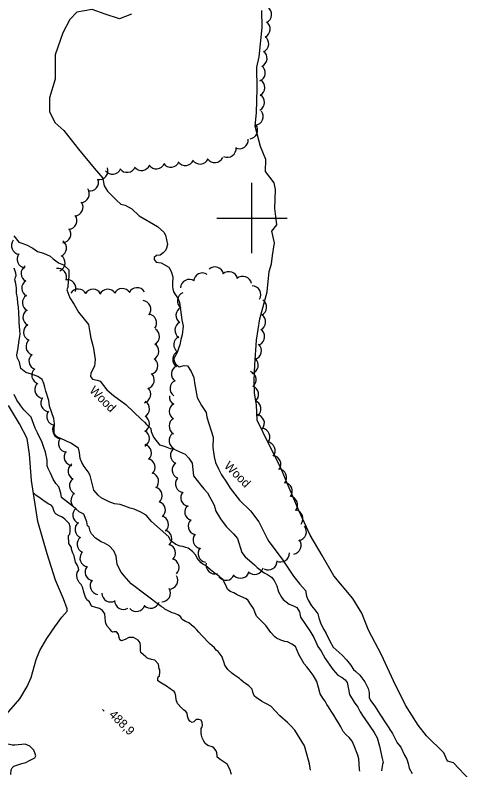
# Model space of a CAD drawing. Extents: x 642515 to 647219, y 6080136 to 6084356.
# Drawn here: x 643919.5 to 644074.3, y 6081612.4 to 6081869.2 of the extents above; entities that cross this region are included whole.
import ezdxf

# ---------------------------------------------------------------- set-up
doc = ezdxf.new("R2010")
doc.units = 0
for name, color, linetype in [('Level 1', 7, 'Continuous'), ('Level 19', 7, 'Continuous'), ('Level 2', 7, 'Continuous'), ('Level 3', 7, 'Continuous'), ('Level 4', 7, 'Continuous'), ('Level 44', 7, 'Continuous'), ('Level 61', 7, 'Continuous')]:
    doc.layers.add(name, color=color, linetype=linetype)

msp = doc.modelspace()

# ---------------------------------------------------------------- linework, layer by layer
at = {"layer": 'Level 1'}
for points in [[(643959.19, 6081869.49), (643955.1, 6081867.87), (643950.17, 6081869.49), (643945.82, 6081871.06), (643940.54, 6081870.21), (643938.14, 6081867.7), (643935.79, 6081863.14), (643933.19, 6081855.71), (643933.19, 6081847.35), (643931.26, 6081841.02), (643931.21, 6081836.42), (643933.07, 6081832.59), (643936.1, 6081829.89), (643941.14, 6081823.52), (643946.44, 6081817.09), (643949.41, 6081813.67)], [(643949.41, 6081813.67), (643949.41, 6081813.67), (643949.66, 6081812.23), (643949.88, 6081811.11), (643950.96, 6081809.23), (643954.05, 6081806.17), (643955.5, 6081804.88), (643956.98, 6081804.47), (643959.32, 6081803.31), (643961.8, 6081800.94), (643968, 6081797.24), (643970.13, 6081795.33), (643970.76, 6081794.32), (643971.42, 6081791.13), (643971.09, 6081789.9), (643970.72, 6081789.15), (643969.96, 6081788.3), (643968.95, 6081787.52), (643967.66, 6081787.45), (643966.81, 6081786.68), (643966.84, 6081786.03), (643967.54, 6081785.1), (643969.26, 6081784.95), (643971.85, 6081783.4), (643972.67, 6081781.91), (643973.25, 6081780.17), (643973.1, 6081777.78), (643973.12, 6081776.77), (643973.2, 6081776.01), (643973.46, 6081775.01), (643975.05, 6081772.6), (643975.52, 6081771.41), (643976.08, 6081767.25), (643976.25, 6081765.56), (643976.7, 6081763.33), (643976.38, 6081760.41), (643975.9, 6081758.85), (643975.6, 6081756.97), (643974.62, 6081754.18), (643973.59, 6081752.35), (643973.72, 6081751.47), (643974.18, 6081750.44), (643975.36, 6081749.54), (643977.04, 6081750.03), (643978.26, 6081749.86), (643979.42, 6081747.91), (643980.35, 6081745.86), (643980.61, 6081744.1), (643981.46, 6081739.06), (643982.99, 6081736.32)], [(643982.99, 6081736.32), (643984.57, 6081733.99), (643984.82, 6081732.39), (643986.9, 6081725.65), (643986.77, 6081722.1), (643987.28, 6081718.9), (643987.71, 6081716.99), (643988.8, 6081714.79), (643989.73, 6081712.74), (643991.48, 6081710.26), (643992.73, 6081708.23), (643995.87, 6081704.21), (643999.63, 6081700.55), (644002.43, 6081696.83), (644005.34, 6081691.18), (644005.88, 6081690.09), (644010.43, 6081684.05), (644014.22, 6081678.37), (644016.48, 6081675.6), (644017.35, 6081674.52), (644018.38, 6081673.44), (644018.65, 6081671.53), (644019.22, 6081670.11), (644020.45, 6081668.24), (644021.5, 6081666.85), (644022.55, 6081665.45), (644022.87, 6081664.1), (644023.54, 6081662.13), (644024.54, 6081660.17), (644025.43, 6081658.77), (644026.53, 6081656.41), (644027.78, 6081654.22), (644028.81, 6081653.31), (644030.85, 6081651.49), (644032.31, 6081649.88), (644033.7, 6081648.18), (644034.68, 6081646.55), (644035.45, 6081645.86), (644036.81, 6081644.65), (644038.56, 6081642.33), (644039.65, 6081640.13), (644039.97, 6081638.78), (644040.07, 6081637.02), (644040.53, 6081636), (644041.92, 6081634.14), (644043.7, 6081631.34), (644047.94, 6081624.81), (644048.57, 6081623.64), (644049.57, 6081621.68), (644050.79, 6081620.13), (644052.07, 6081617.47), (644052.79, 6081616.06)], [(643918.08, 6081610.83), (643918.15, 6081612.43), (643918.51, 6081613.17), (643919.12, 6081613.68), (643920.85, 6081614.26), (643921.88, 6081614.55), (643923.14, 6081614.94), (643924.47, 6081615.57), (643926.26, 6081616.55), (643926.55, 6081617.2), (643926.35, 6081617.83), (643925.96, 6081619.09), (643924.51, 6081620.52), (643922.95, 6081621.16), (643919.44, 6081620.81), (643918.56, 6081620.84), (643915.7, 6081621.56), (643915.14, 6081621.61), (643913.93, 6081621.79), (643911.5, 6081622.13), (643909.86, 6081622.68), (643909.14, 6081622.72), (643907.64, 6081623.6), (643905.57, 6081625.35)], [(644052.79, 6081616.06), (644053.28, 6081614.56), (644053.61, 6081613.05), (644054.68, 6081611.17)]]:
    msp.add_lwpolyline(points, dxfattribs=at)
at = {"layer": 'Level 19'}
msp.add_lwpolyline([(643915.97, 6081630.54), (643921.14, 6081636.58), (643923.62, 6081640.73), (643925.02, 6081643.85), (643926.73, 6081649.99), (643928.01, 6081653.06), (643930.29, 6081657.17), (643933.07, 6081661.13), (643935.48, 6081664.35), (643937.23, 6081666.39), (643937.3, 6081667.25), (643936, 6081670.63), (643933.27, 6081676.97), (643930.51, 6081685.96), (643927.31, 6081696.87), (643925.1, 6081710.9), (643924.49, 6081719.81), (643923.61, 6081725.13), (643921.08, 6081730.08), (643917.33, 6081736.42)], dxfattribs=at)
at = {"layer": 'Level 2'}
for points in [[(643919.07, 6081794.12), (643920.81, 6081791.96), (643921.47, 6081791.67), (643923.37, 6081791.05), (643925.54, 6081789.88), (643927.14, 6081788.76), (643929.19, 6081788.14), (643931.52, 6081787.14), (643932.54, 6081786.23), (643934.31, 6081784.95), (643935.97, 6081784.24), (643937.84, 6081782.57), (643937.81, 6081780.15), (643937.58, 6081778.52), (643937.44, 6081776.66), (643937.17, 6081775.68), (643938.13, 6081772.99), (643939.64, 6081770.74), (643941.16, 6081768.16), (643944.55, 6081763.92), (643944.83, 6081761.84), (643945.29, 6081759.28), (643946, 6081756.83), (643946.22, 6081755.71), (643946.75, 6081752.03), (643946.56, 6081749.77), (643945.32, 6081747.37), (643945.22, 6081746.23), (643945.83, 6081745.38), (643947.47, 6081744.99), (643948.54, 6081744.64), (643950.81, 6081741.7), (643953.02, 6081739.73), (643957.23, 6081736.74), (643962.61, 6081731.64), (643963.63, 6081730.73), (643964.25, 6081729.87), (643965.7, 6081728.58), (643965.83, 6081727.54), (643966.67, 6081725.58), (643968.67, 6081723.03), (643969.17, 6081722.89)], [(643920.07, 6081774.62), (643920.06, 6081776.31), (643919.81, 6081777.9), (643919.5, 6081779.09), (643919.69, 6081779.99), (643919.9, 6081780.56), (643919.77, 6081781.44), (643919.27, 6081783.1)], [(643958.74, 6081701.47), (643956.92, 6081702.17), (643955.28, 6081702.73), (643953.33, 6081702.94), (643951.6, 6081703.57), (643948.86, 6081704.95), (643947.84, 6081705.86), (643946.37, 6081707.62), (643945.65, 6081710.24), (643945.04, 6081712.61), (643944.41, 6081713.79), (643943.71, 6081714.71), (643943.01, 6081715.64), (643942.21, 6081716.96), (643941.65, 6081718.38), (643941.45, 6081720.38), (643941.13, 6081721.89), (643938.53, 6081723.59), (643935.13, 6081725.1), (643934.14, 6081725.53), (643933.55, 6081725.9), (643932.86, 6081726.82), (643932.86, 6081728.19), (643932.91, 6081730.12), (643932.73, 6081731.96), (643931.28, 6081736.14), (643931.01, 6081738.06), (643930.03, 6081741.22), (643929.71, 6081742.57), (643929.32, 6081743.83), (643928.75, 6081745.25), (643927.32, 6081746.22), (643925.18, 6081747.07), (643923.21, 6081747.6), (643921.52, 6081748.96), (643920.99, 6081751.1), (643920.26, 6081752.67), (643920.13, 6081753.55), (643920.51, 6081755.34), (643920.67, 6081756.87), (643920.98, 6081758.58), (643921.27, 6081760.61), (643921.11, 6081761.96), (643920.88, 6081764.61), (643920.91, 6081765.49), (643920.78, 6081767.9), (643920.66, 6081769.98), (643920.52, 6081771.02), (643920.41, 6081772.95), (643920.07, 6081774.62)], [(643970.51, 6081667.12), (643970, 6081667.49), (643969.29, 6081668.05), (643959.03, 6081675.67), (643956.62, 6081678.43), (643955.59, 6081679.66), (643954.31, 6081682.31), (643953.91, 6081685.1), (643953.16, 6081686.98), (643951.54, 6081688.58), (643949.96, 6081689.53), (643948.88, 6081690.04), (643946.88, 6081691.21), (643945.51, 6081692.74), (643945.13, 6081693.68), (643944.74, 6081694.94), (643944.14, 6081695.47), (643943.99, 6081696.83), (643942.95, 6081699.42), (643941.38, 6081700.22), (643939.94, 6081701.5), (643937.41, 6081703.45), (643935.38, 6081705.1), (643935.14, 6081706.53), (643934.37, 6081708.74), (643933.42, 6081709.89), (643932.54, 6081711.29), (643931.62, 6081713.32), (643930.8, 6081714.96), (643930.51, 6081715.83), (643930.4, 6081717.75), (643929.84, 6081720.53), (643929.35, 6081722.03), (643928.67, 6081724.16), (643927.6, 6081726.02), (643927.14, 6081727.04), (643926.4, 6081728.61), (643925.06, 6081732.39), (643924.12, 6081733.3), (643922.55, 6081734.86), (643921.46, 6081736.28), (643921.06, 6081736.94), (643920.18, 6081738.18), (643919.23, 6081740.1)], [(643969.17, 6081722.89), (643970.57, 6081722.41), (643972.3, 6081721.78), (643973.36, 6081721.59), (643977.42, 6081719.8), (643978.63, 6081718.42), (643979.78, 6081716.79), (643980.26, 6081712.39), (643982.7, 6081709.3), (643983.82, 6081708), (643985.03, 6081706.61), (643987.28, 6081702.47), (643987.88, 6081700.41), (643989.4, 6081697.84), (643991.33, 6081695.21), (643993.81, 6081692.69), (643995.19, 6081691.15), (643996.75, 6081686.41), (643997.8, 6081684.86), (643999.33, 6081683.65), (644001.03, 6081682.14), (644001.96, 6081681.3), (644002.81, 6081680.55), (644004.32, 6081679.5), (644005.41, 6081678.84), (644006.75, 6081677.94), (644007.71, 6081676.79), (644008.61, 6081675.07), (644009.21, 6081673.01), (644010.2, 6081671.21), (644010.81, 6081670.36), (644012.76, 6081668.78), (644014.25, 6081668.22), (644015.41, 6081667.64), (644016.29, 6081666.24), (644016.64, 6081664.41), (644019.81, 6081659.76), (644021.14, 6081657.5), (644021.88, 6081655.93), (644022.61, 6081654.36), (644023.67, 6081652.81), (644025.1, 6081650.31), (644026.59, 6081648.07), (644027.73, 6081646.44), (644029.37, 6081644.68), (644030.87, 6081643.8), (644031.88, 6081643.05), (644032.58, 6081642.12), (644033.03, 6081639.89), (644033.37, 6081638.06), (644034.97, 6081635.42), (644036.11, 6081633.79)], [(643950.08, 6081665.47), (643949.25, 6081666.67), (643948.29, 6081667.3), (643946.98, 6081667.71), (643945.59, 6081668.11), (643944.82, 6081669.63), (643943.98, 6081670.31), (643943.67, 6081670.89), (643943.49, 6081671.2), (643943.09, 6081672.54), (643942.45, 6081674.62), (643942, 6081675.48), (643941.36, 6081676.21), (643940.68, 6081677.49), (643940.53, 6081678.76), (643940.61, 6081679.53), (643940.91, 6081679.86), (643941.2, 6081680.52), (643941.16, 6081681.08), (643940.76, 6081681.9), (643940.09, 6081683.1), (643939.68, 6081685.28), (643939.19, 6081686.17), (643938.81, 6081687.12), (643938.75, 6081687.47), (643938.72, 6081688.11), (643937.84, 6081689.42), (643937.84, 6081690.1), (643937.77, 6081691.38), (643937.69, 6081692.14), (643938.14, 6081692.64), (643938.25, 6081693.61), (643938.29, 6081695.09), (643937.94, 6081696.24), (643936.49, 6081697.76), (643935.9, 6081698.13), (643935.28, 6081698.45), (643934.54, 6081698.81), (643933.54, 6081699.4), (643933.07, 6081699.89), (643932.74, 6081700.64), (643932.36, 6081701.74), (643931.76, 6081702.43), (643930.97, 6081702.82), (643929.8, 6081703.64), (643928.51, 6081704.49), (643927.92, 6081704.94), (643927.04, 6081705.57), (643926.57, 6081705.91), (643925.76, 6081706.69)], [(644022.73, 6081640.47), (644022.22, 6081642.45), (644020.97, 6081644.63), (644019.66, 6081646.4), (644018.8, 6081647.48), (644017.93, 6081648.55), (644016.14, 6081651.67), (644014.94, 6081654.41), (644013.69, 6081655.23), (644012.19, 6081655.95), (644011.38, 6081656.06), (644009.98, 6081656.55), (644008.49, 6081657.27), (644007.91, 6081657.64), (644006.53, 6081659.17), (644004.86, 6081661.57), (644003.67, 6081662.63), (644001.7, 6081664.69), (644000.67, 6081667.28), (643999.7, 6081668.76), (643998.9, 6081670.08), (643998.15, 6081670.6), (643996.41, 6081671.39), (643995.09, 6081671.96), (643994, 6081672.62), (643992.76, 6081673.12), (643991.83, 6081673.95), (643991.1, 6081675.51), (643990.28, 6081677.16), (643989.68, 6081677.69), (643989.01, 6081678.29), (643987.75, 6081679.11), (643986.06, 6081680.46), (643984.29, 6081681.89), (643983.37, 6081682.4), (643982.86, 6081682.86), (643981.48, 6081684.39), (643981.02, 6081685.41), (643979.9, 6081686.71), (643978.47, 6081687.84), (643977.64, 6081688.11), (643976.58, 6081688.46), (643975.76, 6081688.57), (643974.28, 6081689.14), (643972.94, 6081690.03), (643972.43, 6081690.48), (643971.87, 6081691.74), (643966.01, 6081696.96), (643964.12, 6081699.11), (643962.28, 6081700.13), (643960.05, 6081701.06), (643958.74, 6081701.47)], [(644019.35, 6081615.77), (644018.76, 6081617.82), (644018.04, 6081620.58), (644014.76, 6081625.93), (644013.39, 6081627.46), (644012.2, 6081628.52), (644009.66, 6081630.78), (644006.54, 6081634.1), (644005.09, 6081634.86), (644004.13, 6081635.33), (644003.34, 6081635.81), (644002.59, 6081636.33), (644001.71, 6081636.96), (644000.91, 6081637.6), (644000.47, 6081638.89), (644000.17, 6081639.92), (643999.06, 6081641.06), (643997.93, 6081641.84), (643997.31, 6081642.25), (643996.37, 6081643.08), (643995.91, 6081643.49), (643995.2, 6081643.98), (643994.24, 6081644.6), (643993.27, 6081645.31), (643991.91, 6081646.52), (643990.86, 6081648.07), (643990.56, 6081649.17), (643990.27, 6081650.04), (643989.98, 6081650.9), (643989.28, 6081651.83), (643988.63, 6081652.71), (643988, 6081653.2), (643987.4, 6081653.89), (643986.46, 6081654.72), (643985.91, 6081655.21), (643983, 6081658.26), (643982.02, 6081659.29), (643981.32, 6081660.21), (643980.69, 6081660.7), (643979.43, 6081661.75), (643978.63, 6081662.39), (643977.51, 6081662.93), (643976.38, 6081663.63), (643976.12, 6081664.02), (643975.8, 6081664.6), (643974.97, 6081665.12), (643973.89, 6081665.62), (643973, 6081665.81), (643971.63, 6081666.5), (643970.51, 6081667.12)], [(643978.5, 6081629.7), (643978.25, 6081630.68), (643978.07, 6081631.75), (643977.59, 6081632.33), (643976.88, 6081632.81), (643976.12, 6081633.49), (643974.75, 6081635.01), (643974.4, 6081636.23), (643974.29, 6081637.47), (643973.99, 6081638.49), (643973.9, 6081638.73), (643973.64, 6081639.11), (643972.26, 6081639.96), (643971.08, 6081640.93), (643969.34, 6081641.88), (643968.16, 6081642.77), (643968.12, 6081643.49), (643968.21, 6081644.1), (643968.64, 6081644.4), (643968.77, 6081645.65), (643968.76, 6081646.49), (643968.62, 6081646.76), (643968.29, 6081648.42), (643967.05, 6081649.75), (643965.91, 6081649.93), (643964.84, 6081650.35), (643964.35, 6081650.57), (643964.05, 6081650.83), (643963.21, 6081651.58), (643962.32, 6081652.3), (643962.16, 6081653.05), (643962.23, 6081654.65), (643962.06, 6081655.64), (643961.4, 6081656.53), (643959.82, 6081657.48), (643959.06, 6081657.48), (643958.3, 6081657.4), (643956.97, 6081656.77), (643955.74, 6081656.34), (643955.16, 6081656.71), (643955, 6081657.46), (643954.73, 6081658.6), (643954.05, 6081659.37), (643953.16, 6081659.4), (643952.72, 6081659.26), (643952.43, 6081659.52), (643951.87, 6081660.17), (643950.93, 6081661.16), (643950.39, 6081662.25), (643950.27, 6081662.96), (643950.24, 6081664.12), (643950.08, 6081665.47)], [(644036.81, 6081611.95), (644036.78, 6081612.59), (644036.6, 6081614.43), (644036.5, 6081616.19), (644036.11, 6081617.45), (644034.96, 6081620.59), (644034.23, 6081622.16), (644033.2, 6081623.39), (644032.18, 6081624.29), (644031.14, 6081625.52), (644030.41, 6081627.09), (644029.61, 6081628.41), (644028.81, 6081629.73), (644028.01, 6081631.05), (644027.13, 6081632.44), (644026.16, 6081633.91), (644025.63, 6081634.69), (644025.09, 6081635.78), (644024.31, 6081636.78), (644023.34, 6081638.25), (644022.73, 6081640.47)], [(644036.11, 6081633.79), (644036.93, 6081632.15), (644037.98, 6081630.6), (644038.6, 6081629.75), (644041.68, 6081625.18), (644042.75, 6081623.31), (644043.55, 6081620.46), (644044.43, 6081616.33), (644044.74, 6081614.98), (644044.53, 6081614.4), (644044.17, 6081612.14)], [(643993.14, 6081610.9), (643992.56, 6081612.63), (643991.66, 6081614.34), (643989.28, 6081616.01), (643988.31, 6081616.8), (643988.29, 6081617.19), (643988.23, 6081618.23), (643987.99, 6081618.9), (643987.17, 6081619.93), (643986.58, 6081620.3), (643985.12, 6081620.7), (643984.27, 6081621.45), (643983.82, 6081622.23), (643983.24, 6081623.36), (643982.95, 6081624.22), (643982.83, 6081624.85), (643982.82, 6081625.85), (643982.82, 6081626.45), (643983.23, 6081627.08), (643983.33, 6081627.52), (643983.19, 6081628.55), (643982.82, 6081629.33), (643982.01, 6081629.61), (643981.17, 6081629.52), (643980.36, 6081628.8), (643979.85, 6081628.57), (643978.99, 6081628.96), (643978.5, 6081629.7)], [(644020.1, 6081612.37), (644019.67, 6081614.43), (644019.35, 6081615.77)]]:
    msp.add_lwpolyline(points, dxfattribs=at)
at = {"layer": 'Level 3'}
msp.add_line((643949.25, 6081632.99), (643949.82, 6081632.43), dxfattribs=at)
at = {"layer": 'Level 4'}
for points in [[(644006.88, 6081795.63), (644008.55, 6081797.86), (644008.23, 6081800.63), (644007.9, 6081803.4), (644008.1, 6081809.89), (644007.73, 6081812.09), (644004.79, 6081815.95), (644004.88, 6081820.06), (644003.07, 6081824.47), (644001.27, 6081831.35), (644001.73, 6081836.05), (644001.92, 6081844.1), (644001.82, 6081851.49), (644002.6, 6081854.98), (644003.58, 6081864.96), (644003.49, 6081870.78)], [(644074.3, 6081608.88), (644068.71, 6081614.8), (644066.72, 6081615.35), (644065.4, 6081618.22), (644059.57, 6081624.04), (644056.74, 6081627.65), (644052.41, 6081634.46), (644048.25, 6081642.67), (644044.21, 6081651.54), (644039.78, 6081659.98), (644037.48, 6081665.75), (644034.48, 6081670.74), (644027.97, 6081678.42), (644024.04, 6081685.33), (644019.95, 6081692.24), (644016.1, 6081700.63), (644012.11, 6081709.92), (644009.83, 6081715.37), (644005.84, 6081723.27), (644001.92, 6081731.41), (644001.7, 6081736.56), (644001.06, 6081740.55), (644000.89, 6081744.88), (644001.15, 6081750.22), (644001.74, 6081758.54), (644002.87, 6081765.89), (644005.29, 6081775.05), (644006.03, 6081781.97), (644006.78, 6081784.56), (644007.11, 6081787.36), (644007.85, 6081791.67), (644006.88, 6081795.63)]]:
    msp.add_lwpolyline(points, dxfattribs=at)
at = {"layer": 'Level 44'}
for centre, start, end in [((644003.84, 6081869.4), 294.4068, 54.3847), ((644003.35, 6081864.42), 294.4068, 54.3847), ((644002.86, 6081859.45), 294.4068, 54.3847), ((644002.28, 6081854.49), 293.2607, 53.2386), ((644001.69, 6081849.52), 293.2607, 53.2386), ((644001.51, 6081844.5), 298.9812, 58.9591), ((644001.41, 6081839.5), 298.6058, 58.5837), ((644000.98, 6081834.68), 277.7597, 37.7376), ((643999.09, 6081830.05), 277.7597, 37.7376), ((643995.85, 6081826.71), 245.1509, 5.1289), ((643991.76, 6081823.83), 245.1509, 5.1289), ((643987.46, 6081821.98), 215.644, 335.622), ((643962.59, 6081819.32), 217.5248, 337.5028), ((643967.56, 6081819.88), 216.3737, 336.3516), ((643972.53, 6081820.43), 216.3737, 336.3516), ((643977.5, 6081820.99), 216.3737, 336.3516), ((643982.48, 6081821.49), 215.644, 335.622), ((643948.12, 6081816.19), 260.4256, 20.4036), ((643952.67, 6081818.01), 217.5248, 337.5028), ((643957.63, 6081818.67), 217.5248, 337.5028), ((643944.93, 6081812.33), 260.4256, 20.4036), ((643941.8, 6081808.35), 274.786, 34.7639), ((643939.67, 6081803.83), 274.786, 34.7639), ((643937.58, 6081799.28), 275.6485, 35.6264), ((643935.52, 6081794.73), 275.6485, 35.6264), ((643921.31, 6081790.77), 142.5571, 262.5351), ((643934.05, 6081789.91), 294.1023, 54.0802), ((643923.23, 6081786.15), 142.5571, 262.5351), ((643933.54, 6081784.94), 294.1023, 54.0802), ((643924.59, 6081781.3), 122.4262, 242.4042), ((643934.08, 6081780.04), 339.3343, 99.3122), ((643987.55, 6081780.49), 11.423, 131.4009), ((643983.29, 6081778.48), 56.465, 176.4429), ((643992.29, 6081778.9), 11.423, 131.4009), ((643997.03, 6081777.3), 11.423, 131.4009), ((643924.8, 6081776.3), 122.4262, 242.4042), ((643937.25, 6081776.17), 339.3343, 99.3122), ((643978.81, 6081776.26), 56.465, 176.4429), ((644000.12, 6081774.11), 327.9463, 87.9242), ((643941.03, 6081773), 29.058, 149.0359), ((643946.03, 6081772.92), 29.058, 149.0359), ((643951.05, 6081772.9), 33.0999, 153.0779), ((643956.04, 6081773.17), 33.0999, 153.0779), ((643961.04, 6081773.44), 33.0999, 153.0779), ((643977.77, 6081771.98), 113.6198, 233.5977), ((643925.01, 6081771.31), 122.4262, 242.4042), ((643962.74, 6081769.06), 323.3326, 83.3106), ((644002.14, 6081769.8), 296.1639, 56.1419), ((643977.25, 6081767.02), 115.9306, 235.9086), ((643925.22, 6081766.31), 122.4262, 242.4042), ((643964.72, 6081764.47), 323.3326, 83.3106), ((644001.81, 6081764.81), 296.1639, 56.1419), ((643976.9, 6081762.03), 115.9306, 235.9086), ((643925.43, 6081761.32), 122.4262, 242.4042), ((643965.66, 6081759.82), 297.3684, 57.3464), ((644001.47, 6081759.82), 296.1639, 56.1419), ((643976.54, 6081757.04), 115.9306, 235.9086), ((643926.26, 6081756.44), 131.3853, 251.3632), ((643965.43, 6081754.83), 297.3684, 57.3464), ((644000.39, 6081754.98), 287.408, 47.3859), ((643976.18, 6081752.05), 115.9306, 235.9086), ((643927.25, 6081751.54), 131.3853, 251.3632), ((643965.13, 6081749.9), 285.927, 45.9049), ((643999.3, 6081750.11), 287.408, 47.3859), ((643928.23, 6081746.64), 131.3853, 251.3632), ((643975.72, 6081747.07), 114.6727, 234.6506), ((643963.91, 6081745.05), 285.927, 45.9049), ((643998.59, 6081745.1), 309.3326, 69.3105), ((643975.25, 6081742.09), 114.6727, 234.6506), ((643929.27, 6081741.82), 143.7523, 263.7302), ((643962.7, 6081740.2), 285.927, 45.9049), ((643999.4, 6081740.17), 309.3326, 69.3105), ((643931.28, 6081737.24), 143.7523, 263.7302), ((643975.02, 6081739.37), 174.8665, 239.7875), ((643962.29, 6081735.18), 299.6507, 59.6287), ((643975, 6081734.37), 119.8095, 239.7875), ((644000.21, 6081735.23), 309.3326, 69.3105), ((643933.29, 6081732.67), 143.7523, 263.7302), ((643962.26, 6081730.18), 299.6507, 59.6287), ((643974.94, 6081729.37), 119.3696, 239.3476), ((644001.37, 6081730.33), 321.4643, 81.4422), ((643935.3, 6081728.09), 143.7523, 263.7302), ((644003.2, 6081725.68), 321.4643, 81.4422), ((643962.22, 6081725.18), 299.6507, 59.6287), ((643974.91, 6081724.41), 126.1224, 246.1004), ((643937.27, 6081723.49), 143.1586, 263.1365), ((644005.03, 6081721.02), 321.4643, 81.4422), ((643939.24, 6081718.89), 143.1586, 263.1365), ((643962.95, 6081720.2), 314.1567, 74.1347), ((643975.44, 6081719.43), 126.1224, 246.1004), ((643964.17, 6081715.35), 314.1567, 74.1347), ((644006.98, 6081716.41), 323.052, 83.03), ((643940.57, 6081714.04), 125.6182, 245.5961), ((643975.97, 6081714.46), 126.1224, 246.1004), ((643965.39, 6081710.5), 314.1567, 74.1347), ((644008.94, 6081711.81), 323.052, 83.03), ((643941.05, 6081709.06), 125.6182, 245.5961), ((643977.11, 6081709.72), 141.0727, 261.0506), ((643966.61, 6081705.65), 314.1567, 74.1347), ((644010.9, 6081707.21), 323.052, 83.03), ((643941.54, 6081704.09), 125.6182, 245.5961), ((643978.9, 6081705.05), 141.0727, 261.0506), ((644012.7, 6081702.56), 321.0769, 81.0548), ((643967.67, 6081700.77), 312.2112, 72.1891), ((643942.2, 6081699.14), 128.2724, 248.2503), ((643980.27, 6081700.21), 133.5836, 253.5615), ((644014.5, 6081697.89), 321.0769, 81.0548), ((643968.73, 6081695.89), 312.2112, 72.1891), ((643981.44, 6081695.35), 133.5836, 253.5615), ((643942.92, 6081694.2), 128.2724, 248.2503), ((644015.67, 6081693.44), 278.9365, 38.9145), ((643969.9, 6081691.02), 314.135, 74.1129), ((643983.08, 6081690.67), 140.4912, 260.4691), ((643943.63, 6081689.25), 128.2724, 248.2503), ((644013.87, 6081688.78), 278.9365, 38.9145), ((643971.12, 6081686.17), 314.135, 74.1129), ((643984.83, 6081685.99), 140.4912, 260.4691), ((643944.6, 6081684.43), 140.4967, 260.4746), ((644009.88, 6081686.14), 242.6478, 2.6257), ((643972.34, 6081681.32), 314.135, 74.1129), ((643987.49, 6081682.1), 168.2561, 288.234), ((644005.67, 6081683.45), 242.6478, 2.6257), ((643946.35, 6081679.74), 140.4967, 260.4746), ((643996.22, 6081680.6), 225.167, 345.145), ((644001.04, 6081681.91), 225.167, 345.145), ((643948.1, 6081675.06), 140.4967, 260.4746), ((643971.92, 6081676.92), 270.1754, 30.1534), ((643991.31, 6081679.9), 217.134, 337.1119), ((643952.09, 6081672.53), 179.5749, 299.5529), ((643969.43, 6081672.58), 270.1754, 30.1534), ((643956.4, 6081669.99), 179.5749, 299.5529), ((643965.66, 6081670.4), 222.7321, 342.71), ((643960.78, 6081669.3), 222.7321, 342.71)]:
    msp.add_arc(centre, 3, start, end, dxfattribs=at)
at = {"layer": 'Level 61'}
for p, q in [((644000, 6081812.16), (644000, 6081788.16)), ((644012.16, 6081800), (643988.16, 6081800))]:
    msp.add_line(p, q, dxfattribs=at)

# ---------------------------------------------------------------- texts
at = {"layer": 'Level 3'}
msp.add_text('488,9', height=3, rotation=315.59, dxfattribs=at).set_placement((643951.28, 6081630.95))
at = {"layer": 'Level 44'}
for p in [(643944.6, 6081741.23), (643990.45, 6081715.58)]:
    msp.add_text('Wood', height=3, rotation=315.1749, dxfattribs=at).set_placement(p)

doc.saveas('drawing.dxf')
